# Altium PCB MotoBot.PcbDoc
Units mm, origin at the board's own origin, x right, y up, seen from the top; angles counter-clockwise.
Board outline 90.25 x 50.25 mm, 2 copper layers (Top Layer, Bottom Layer); 45 components, 34 nets, 155 pads, 10 vias.
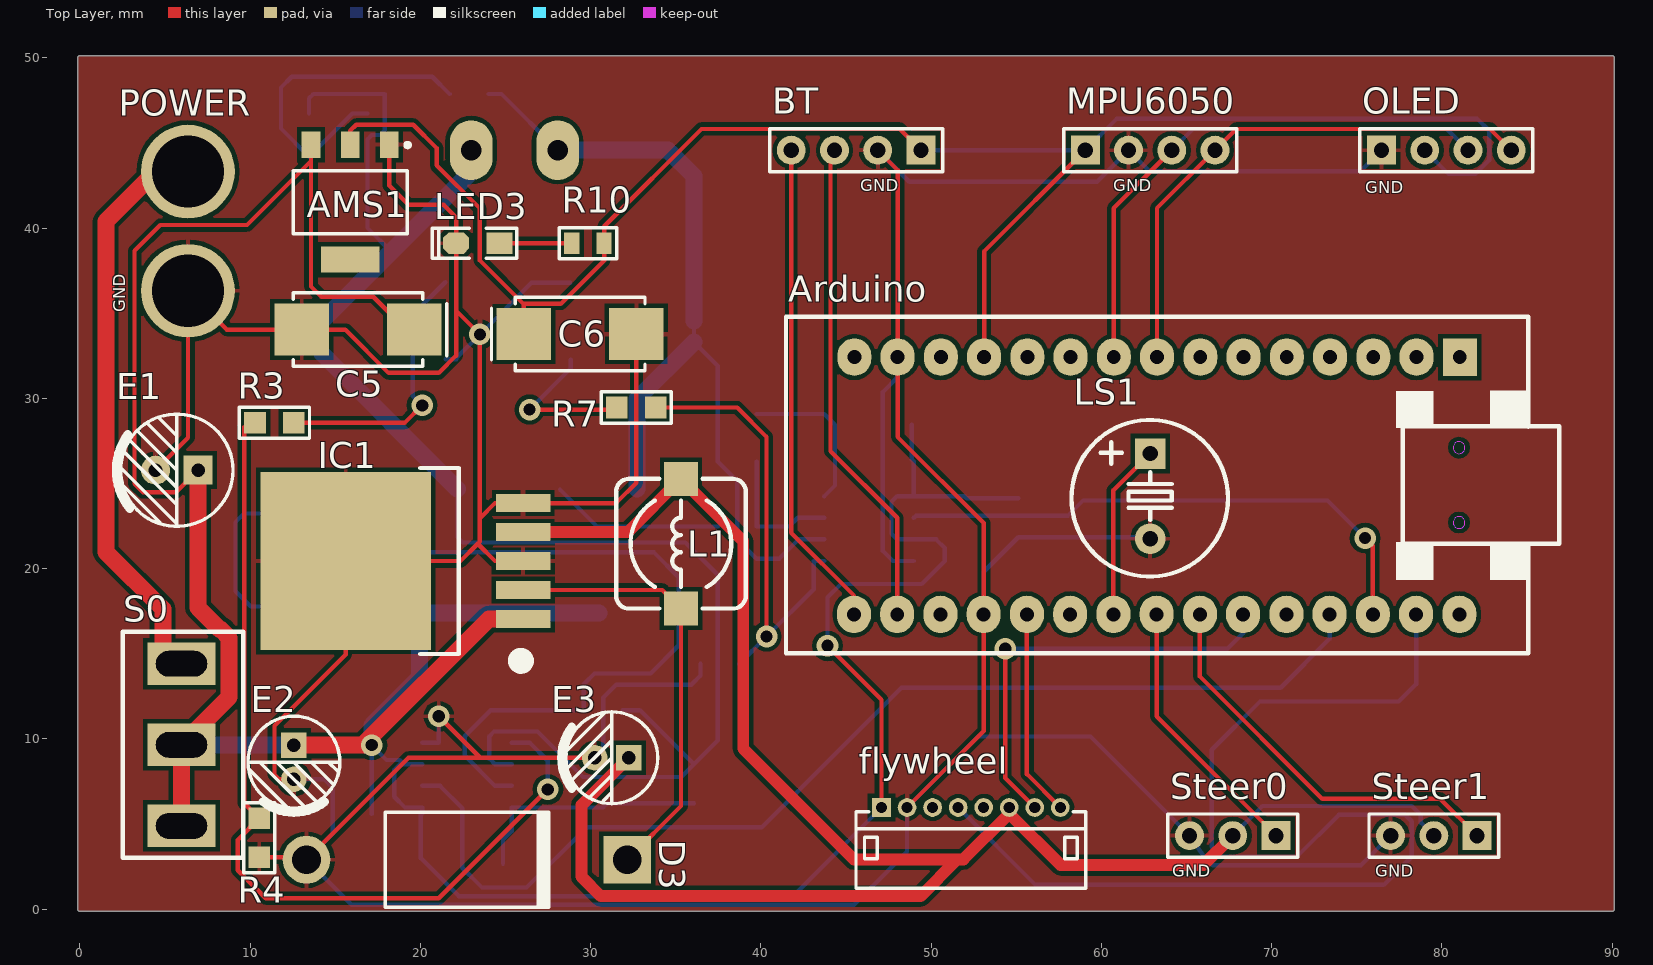
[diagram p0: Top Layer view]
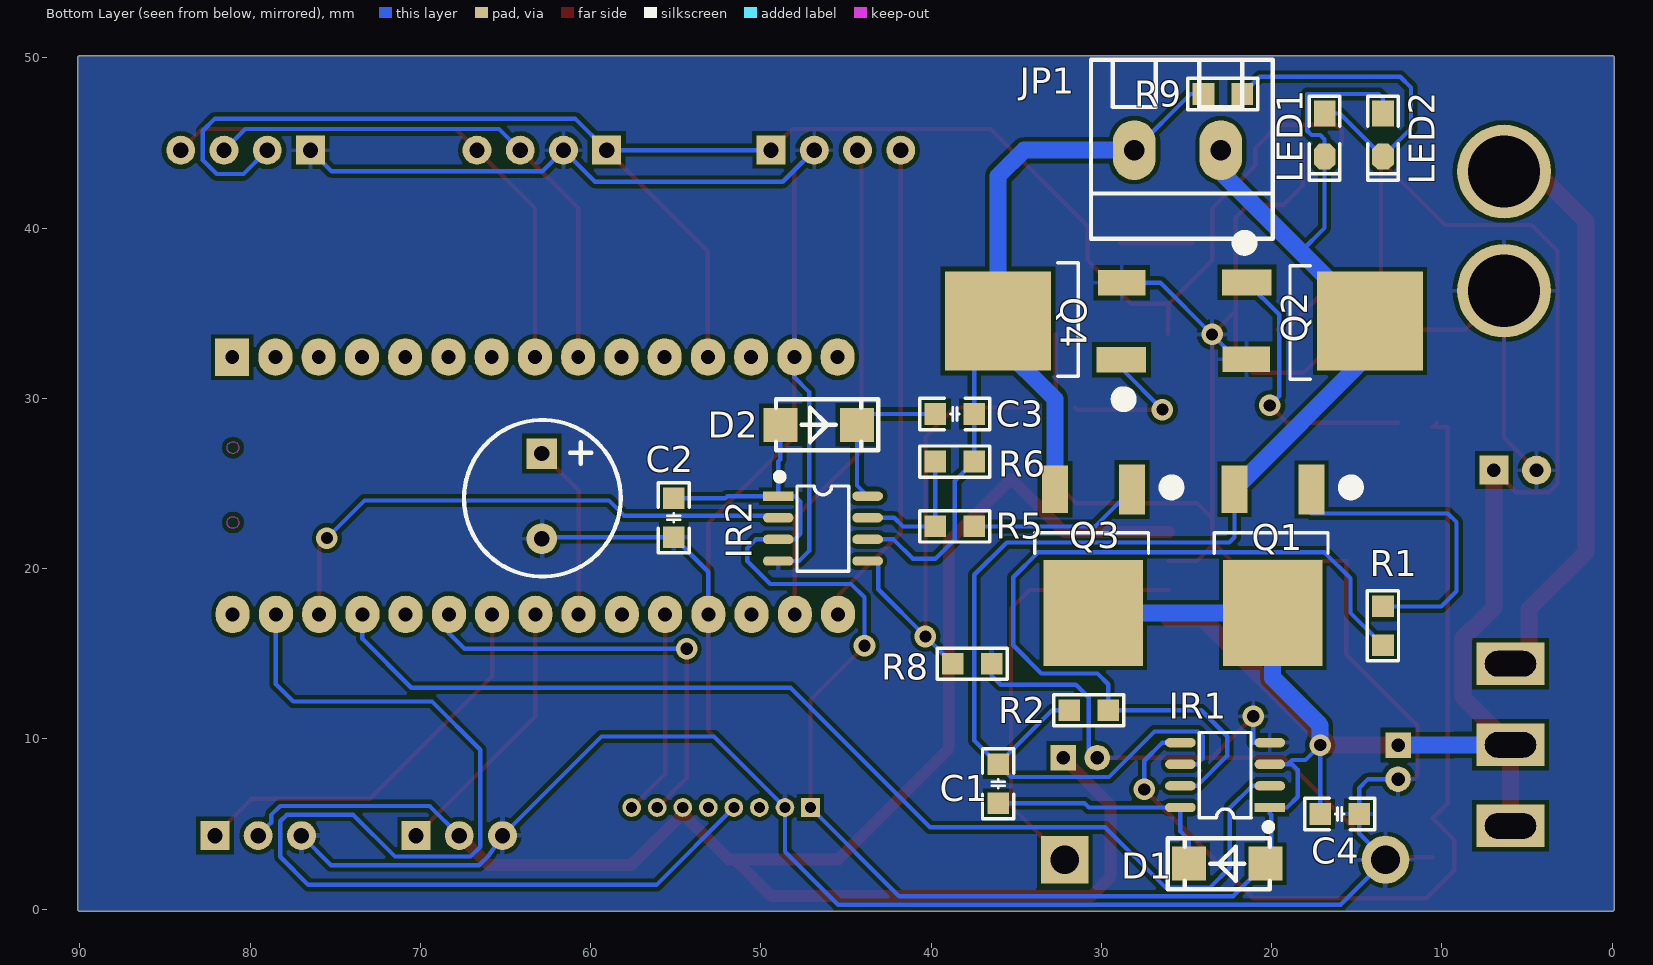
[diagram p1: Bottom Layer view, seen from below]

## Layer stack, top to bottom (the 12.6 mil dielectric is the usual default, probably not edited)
Top Solder: solder mask 0.0102, Solder Resist, Dk 3.5
Top Layer: signal copper 0.0356
Dielectric 1: dielectric 0.32, FR-4, Dk 4.8
Bottom Layer: signal copper 0.0356
Bottom Solder: solder mask 0.0102, Solder Resist, Dk 3.5

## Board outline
0,-0.127 cw(c0,0) -0.127,0 -0.127,50 cw(c0,50) 0,50.127 90,50.127 cw(c90,50) 90.127,50 90.127,0 cw(c90,0) 90,-0.127

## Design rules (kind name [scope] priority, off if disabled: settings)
Clearance [All] p1: gap=0.254 ignorepadtopadclearanceinfootprint=FALSE except(0: Arc-Hole Track-Hole SMDPad-Hole THPad-Hole Via-Hole Fill-Hole Poly-Hole Region-Hole Text-Hole)
PolygonConnect [All] p1: connectstyle=Relief reliefconductorwidth=0.254 reliefentries=4 polygonreliefangle="90 Angle" airgapwidth=0.254
RoutingVias [All] p1: holewidth=0.711 width=1.27 viastyle="Through Hole" minholewidth=0.711 minwidth=1.27 maxholewidth=0.711 maxwidth=1.27
SolderMaskExpansion [All] p1: expansion=0.102
Width [All] p1: maxlimit=2 minlimit=0.254 preferedwidth=0.254 minimp=50.000000 maximp=50.000000 favimp=50.000000
30 further rules are at their usual default settings.

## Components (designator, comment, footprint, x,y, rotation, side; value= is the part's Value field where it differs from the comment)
AMS1 "AMS1117-5V" SOT-223 15.875,41.529 r180 top
Arduino "NANO" NANO 81.051,32.426 r270 top
BT "HDR-1X4" HDR-1X4_M 49.403,44.577 r180 top
C1 "1u" "C 0805_M" 36.068,7.366 r270 bottom
C2 "0.1u" "C 0805_M" 55.118,22.987 r90 bottom
C3 "1u" "C 0805_M" 38.608,29.083 r0 bottom
C4 "0.1u" "C 0805_M" 16.002,5.588 r0 bottom
C5 "Cap Pol" CAP-7343 16.334,34.036 r180 top value=10uF
C6 "Cap Pol" CAP-7343 29.386,33.782 r0 top value=10uF
D1 "SS14" SMA 22.606,2.667 r0 bottom
D2 "SS14" SMA 46.609,28.448 r180 bottom
D3 "Diode 1N5825" DO-201AD 22.733,2.9 r0 top
E1 "220uF/16V" "CAP 2.5*6.3*7" 5.695,25.781 r180 top
E2 "680uF/25V" "CAP 2.0*5*11" 12.573,8.636 r270 top
E3 "220uF/25V" "CAP 2.0*5*11" 31.242,8.89 r180 top
flywheel "HDR-1X8" ZH1.5-WI-8P 52.337,5.969 r0 top
IC1 "LM2596-5.0V" TO263-5A 26.035,20.447 r90 top
IR1 "IR2104" SOP8_N 22.733,7.874 r0 bottom
IR2 "IR2104" SOP8_N 46.355,22.352 r180 bottom
JP1 "HDR-1X2" KF128-5.08-2P 22.987,44.577 r0 bottom
L1 "33uH" CDRH74 35.306,21.463 r90 top
LED1 "" "LED 0805R" 16.891,45.466 r270 bottom
LED2 "" "LED 0805R" 13.462,45.466 r270 bottom
LED3 "红色" "LED 0805W" 23.368,39.116 r180 top
LS1 "DC5V" "BEEP 5x9x5.5" 62.865,24.257 r180 top
MPU6050 "HDR-1X4" HDR-1X4_M 59.055,44.577 r0 top
OLED "HDR-1X4" HDR-1X4_M 76.454,44.577 r0 top
POWER "XT60" XT60 6.35,43.322 r0 top
Q1 "IRLR7843" TO252 19.939,21.599 r0 bottom
Q2 "IRLR7843" TO252 18.415,34.544 r270 bottom
Q3 "IRLR7843" TO252 30.48,21.599 r0 bottom
Q4 "IRLR7843" TO252 31.868,34.544 r90 bottom
R1 "30" "R 0805_M" 13.462,16.637 r90 bottom
R2 "10K" "R 0805_M" 30.734,11.684 r180 bottom
R3 "30" "R 0805_M" 11.43,28.575 r0 top
R4 "10K" "R 0805_M" 10.541,4.191 r90 top
R5 "30" "R 0805_M" 38.608,22.479 r180 bottom
R6 "10K" "R 0805_M" 38.608,26.289 r0 bottom
R7 "30" "R 0805_M" 32.688,29.464 r180 top
R8 "10K" "R 0805_M" 37.592,14.414 r0 bottom
R9 "2K" "R 0805_M" 22.86,47.879 r180 bottom
R10 "200R" "R 0805_L" 29.845,39.116 r0 top
S0 "Switcher" ThreeSwitcher 5.969,14.414 r90 top
Steer0 "HDR-1X3" HDR-1X3 70.256,4.318 r180 top
Steer1 "HDR-1X3" HDR-1X3 82.067,4.318 r180 top

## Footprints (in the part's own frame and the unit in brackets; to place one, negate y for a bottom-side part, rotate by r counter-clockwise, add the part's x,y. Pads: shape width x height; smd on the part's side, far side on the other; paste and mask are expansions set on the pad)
"BEEP 5x9x5.5" [mm] "5*9*5.5mm(脚距,直径,高度)"
  rect 1.8x1.8 hole 0.9: 1(0,-2.5)
  round 1.8 hole 0.9: 2(0,2.5)
  silkscreen extent -4.58,-4.47 4.62,4.72, body extent -4.5,-4.5 4.5,4.5, height 5.45
"C 0805_M" [mil] "无极性贴片电容"
  rect 50x50 smd: 1(-45,0) 2(45,0)
  silkscreen extent -81,-36 81,36, body extent -39,-24 39,24, height 20
"CAP 2.0*5*11" [mm] "脚距2mm直径5mm高度11mm"
  rect 1.5x1.5 hole 0.8: 1(-1,0)
  round 1.5 hole 0.8: 2(1,0)
  silkscreen extent -2.7,-2.7 2.96,2.7, body extent -2.5,-2.5 2.51,2.5, height 11.04
"CAP 2.5*6.3*7" [mm] "脚距2.5mm直径6.3mm高度7mm"
  rect 1.7x1.7 hole 0.8: 1(-1.25,0)
  round 1.7 hole 0.8: 2(1.25,0)
  silkscreen extent -3.3,-3.3 3.56,3.3, body extent -3.15,-3.15 3.16,3.15, height 7.03
CAP-7343 [mm] "钽电容"
  rect 3.2x3.05 smd: 1(-3.302,0) 2(3.302,0)
  silkscreen extent -5.21,-2.16 3.81,2.16, body extent -3.68,-1.91 3.68,1.91, height 2.95
CDRH74 [mm] "7.3*7.3*4.5mm（长宽高）"
  rect 2x2 smd: 1(-3.81,0) 2(3.81,0)
  silkscreen extent -3.81,-3.81 3.81,3.81, body extent -3.65,-3.65 3.65,3.65, height 4.5
DO-201AD [mm] "Diode, Axial; Body 9.5 x 5.6 mm (LxDia. max), Lead Dia. 1.32 mm (max)"
  round 2.8 hole 1.7: 1(-9.42,0)
  rect 2.8x2.8 hole 1.7: 2(9.42,0)
  silkscreen extent -4.8,-2.8 4.9,2.8
HDR-1X3 [mm] "排针，3脚"
  rect 1.7x1.7 hole 0.9: 1(0,0)
  round 1.7 hole 0.9: 2(2.54,0) 3(5.08,0)
  silkscreen extent -1.27,-1.27 6.35,1.27, body extent -1.27,-1.27 6.35,1.27, height 8.5
HDR-1X4_M [mm] "排母，4脚"
  rect 1.7x1.7 hole 0.9: 1(0,0)
  round 1.7 hole 0.9: 2(2.54,0) 3(5.08,0) 4(7.62,0)
  silkscreen extent -1.27,-1.27 8.89,1.27, body extent -1.27,-1.27 8.89,1.27, height 8.5
KF128-5.08-2P [mm] "螺钉式接线端子，脚距5.08mm"
  oval 2.5x3.5 hole 1.2: 1(0,0) 2(5.08,0)
  silkscreen extent -3.05,-5.31 7.62,5.21, body extent -3.04,-5.3 7.62,5.2, height 14.15
"LED 0805R" [mil] "红色0805LED"
  rect 60x50 smd: 1(-50,0)
  oct 60x50 smd: 2(50,0)
  silkscreen extent -90,-35 105,35, body extent -39,-25 39,25, height 32
"LED 0805W" [mil] "白色0805LED"
  rect 60x50 smd: 1(-50,0)
  oct 60x50 smd: 2(50,0)
  silkscreen extent -90,-35 105,35, body extent -39,-25 39,25, height 32
NANO [mm]
  oval 2.2x2 hole 0.813: 1(15.113,-35.585) 2(15.113,-33.045) 3(15.113,-30.505) 4(15.113,-27.965) 5(15.113,-25.425) 6(15.113,-22.885) 7(15.113,-20.345) 8(15.113,-17.805) 9(15.113,-15.265) 10(15.113,-12.725) 11(15.113,-10.185) 12(15.113,-7.645) 13(15.113,-5.105) 14(15.113,-2.565) 15(15.113,-0.025) 17(0,-2.54) 18(0,-5.08) 19(0,-7.62) 20(0,-10.16) 21(0,-12.7) 22(0,-15.24) 23(0,-17.78) 24(0,-20.32) 25(0,-22.86) 26(0,-25.4) 27(0,-27.94) 28(0,-30.48) 29(0,-33.02) 30(0,-35.56)
  rect 2.2x2 hole 0.813: 16(0,0)
  Keep-Out Layer circle w0.05: c5.319,-0.05 r0.35
  Keep-Out Layer circle w0.05: c9.719,-0.05 r0.35
  silkscreen extent -2.36,-39.57 17.4,5.85
"R 0805_L" [mil] "1/8W贴片电阻"
  rect 35x50 smd: 1(-37.4,0) 2(37.4,0)
  silkscreen extent -67,-36 67,36, body extent -39,-25 39,25, height 20
"R 0805_M" [mil] "1/8W贴片电阻"
  rect 50x50 smd: 1(-45,0) 2(45,0)
  silkscreen extent -81,-36 81,36, body extent -39,-25 39,25, height 20
SMA [mm]
  rect 2x2 smd: 1(-2.25,0) 2(2.25,0)
  silkscreen extent -2.5,-1.5 3.5,1.5, body extent -2.5,-1.35 2.5,1.35, height 2.15
SOP8_N [mm] "5*6*1.8mm（长宽高）"
  rect 1.8x0.55 smd: 1(-2.625,1.905)
  oval 1.8x0.55 smd: 2(-2.625,0.635) 3(-2.625,-0.635) 4(-2.625,-1.905) 5(2.625,-1.905) 6(2.625,-0.635) 7(2.625,0.635) 8(2.625,1.905)
  silkscreen extent -2.69,-2.5 1.52,3.2, body extent -3,-2.5 3,2.5, height 1.9
SOT-223 [mm]
  rect 1.1x1.55 smd: 1(-2.3,-3.375) 2(0,-3.375) 3(2.3,-3.375)
  rect 3.45x1.55 smd: 4(0,3.375)
  silkscreen extent -3.5,-3.48 3.35,1.85, body extent -3.3,-3.94 3.3,3.43, height 0.8
ThreeSwitcher [mm]
  rect 2.5x4 hole 1.5 slot 3 at 90 deg: 1(0,0) 2(-4.763,0) 3(-9.525,0)
  silkscreen extent -11.4,-3.62 1.87,3.45
TO252 [mil] "252晶体管"
  rect 60x115 smd: 1(-89.55,-119.77)
  rect 230x245 smd: 2(0,165.35)
  rect 60x110 smd: 3(88.45,-120.77)
  silkscreen extent -196,-140 135,28, body extent -127,-120 129,251, height 91
TO263-5A [mm] "263，5脚晶体管"
  rect 1.05x3.2 smd: 1(-3.4,0) 2(-1.7,0) 3(0,0) 4(1.7,0) 5(3.4,0)
  rect 10.45x10 smd: 3(0,10.414)
  silkscreen extent -6.24,-0.25 5.46,6.04, body extent -5,-0.01 5,13.32, height 4.5
XT60 [mm]
  round 5.5 hole 4.25: 0(0,0) 1(0,-7)
ZH1.5-WI-8P [mm] "长：13.5，宽：4.5，高：3.6"
  rect 1.1x1.1 hole 0.65: 1(-5.25,0)
  round 1.1 hole 0.65: 2(-3.75,0) 3(-2.25,0) 4(-0.75,0) 5(0.75,0) 6(2.25,0) 7(3.75,0) 8(5.25,0)
  silkscreen extent -6.75,-4.75 6.75,-0.25, body extent -6.75,-4.75 6.75,0.25, height 3.65

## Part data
AMS1: library part AMS1117, "三端稳压芯片"
BT MPU6050 OLED: library part "Header 4", "4P接插件"
C1 C2 C3 C4: library part C, "无极性贴片电容"
C5 C6: "极性电解电容"
D1 D2: "肖特基二极管"
D3: library part "Diode 1N5406", "是1N5825，不是1N5406"
E1 E2 E3: library part C-CAP, "直插电解电容"
flywheel: library part "Header 8", "8P接插件"
IC1: library part LM2596-5.0, "DC降压芯片"
IR1 IR2: "电机驱动芯片"
JP1: library part "Header 2", "2P接插件"
L1: library part Inductor
LED1 LED2 LED3: library part LED-SMD, "贴片LED"
LS1: library part BEEP, "蜂鸣器"
Q1 Q2 Q3 Q4: "N沟场效应管"
R1 R2 R3 R4 R5 R6 R7 R8 R9 R10: library part R, "贴片电阻"
S0: library part 3_Switcher
Steer0 Steer1: library part "Header 3", "3P接插件"

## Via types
v1: diameter 1.27, hole 0.711, Top Layer to Bottom Layer, 10 vias

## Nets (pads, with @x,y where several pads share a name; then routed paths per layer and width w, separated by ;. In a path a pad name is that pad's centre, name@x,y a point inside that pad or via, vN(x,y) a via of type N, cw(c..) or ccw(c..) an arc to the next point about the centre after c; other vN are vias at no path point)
3.3V: flywheel.3
+5: AMS1.2 Arduino.27 BT.1 C6.1 MPU6050.1 OLED.2 R10.2 | length 106.2
  Top Layer w0.254: AMS1.2 15.875,45.72 16.231,46.076 19.583,46.076 20.955,44.704 20.955,43.688 23.495,41.148 23.495,38.1 26.06,35.535 ; BT.1 48.158,45.822 36.51,45.822 30.795,40.107 R10.2 30.795,38.1 28.255,35.56 26.084,35.56 26.06,35.535 ; Arduino.27 53.111,38.633 MPU6050.1 ; 26.06,35.535 26.084,35.511 C6.1 26.06,35.535
  Bottom Layer w0.254: BT.1 MPU6050.1 60.909,46.431 82.067,46.431 82.779,45.72 82.779,43.993 81.966,43.18 80.391,43.18 OLED.2
"+5 POWER": E3.1 flywheel.6 IC1.4 L1.2 Steer0.2 Steer1.2 | length 107.9
  Top Layer w0.7: IC1.4 32.18,22.147 L1.2 38.964,21.615 38.964,9.423 45.466,2.921 51.539,2.921 ; E3.1 29.464,6.112 29.464,1.905 30.607,0.762 49.38,0.762 51.539,2.921 ; flywheel.6 flywheel.6@54.587,5.611 ; Steer0.2 65.989,2.591 57.607,2.591 flywheel.6@54.587,5.611 ; 51.539,2.921 51.898,2.921 flywheel.6@54.587,5.611
  Bottom Layer w0.254: Steer0.2 69.455,6.057 78.232,6.057 78.765,5.524 78.765,5.08 Steer1.2
+12: AMS1.3 C2.2 C4.2 C5.1 D1.1 D2.1 E1.1 E2.1 flywheel.1 IC1.1 IR1.1 IR1.3 IR2.1 IR2.3 Q1.2 Q3.2 S0.2 S0.3 | length 196.4
  Top Layer w0.254: AMS1.3 13.575,43.942 ; C5.1 19.165,34.036 17.235,35.966 14.185,35.966 13.575,36.576 13.575,43.942 ; v1(43.917,15.469) 47.087,12.298 flywheel.1 ; E1.1@6.934,25.77 6.934,25.781 E1.1 E1.1@6.934,25.77 ; E1.1@6.934,25.77 5.65,24.486 3.708,24.486 3.214,24.98 3.214,38.672 4.724,40.183 9.816,40.183 13.575,43.942
  Top Layer w1: S0.3 S0.2 8.771,12.454 8.771,15.929 8.281,16.419 8.219,16.419 6.934,17.704 E1.1@6.934,25.77 ; E2.1 v1@16.621,9.636 ; v1(17.145,9.636) v1@16.621,9.636 ; IC1.1 24.032,17.047 v1@16.621,9.636
  Bottom Layer w0.254: C4.2 v1(17.145,9.636) 18.018,8.763 18.796,8.763 19.05,8.509 ; IR1.3 19.05,8.509 ; v1(43.917,15.469) 43.917,18.313 44.704,19.101 49.454,19.101 50.8,20.447 50.8,21.209 50.292,21.717 IR2.3 48.006,21.717 47.676,22.047 47.676,23.927 48.006,24.257 IR2.1 ; flywheel.1 41.88,0.762 22.261,0.762 D1.1 20.025,2.998 20.025,5.535 20.108,5.618 IR1.1 19.101,5.969 18.466,6.604 18.466,8.179 18.796,8.509 19.05,8.509 ; D2.1 48.859,26.41 48.98,26.289 IR2.1 ; C2.2 52.095,24.13 51.968,24.257 IR2.1
  Bottom Layer w1: S0.2 9.271,9.652 9.287,9.636 E2.1 ; v1(17.145,9.636) 17.145,10.795 19.939,13.589 Q1.2 Q3.2
A_PHASE: Arduino.5 flywheel.8 | length 12.2
  Top Layer w0.254: Arduino.5 55.626,7.93 flywheel.8
B_PHASE: Arduino.10 flywheel.7 | length 25.5
  Top Layer w0.254: v1(54.356,15.291) 54.356,7.7 flywheel.7
  Bottom Layer w0.254: v1(54.356,15.291) 67.412,15.291 68.326,16.205 Arduino.10
BEEP: Arduino.7 LS1.1 | length 10.3
  Top Layer w0.254: Arduino.7 60.706,24.598 LS1.1
GND: AMS1.1 Arduino.4 Arduino.29 BT.2 C2.1 C4.1 C5.2 C6.2 D3.1 E1.2 E2.2 E3.2 flywheel.2 IC1.3 IC1.5 IR1.4 IR2.4 LED3.2 LS1.2 MPU6050.2 OLED.1 POWER.1 Q2.3 Q4.3 R4.1 R8.1 Steer0.3 Steer1.3 | length 336.7
  Top Layer w0.254: E1.2 6.35,27.686 POWER.1 8.636,34.036 C5.2 15.596,34.036 18.136,31.496 21.082,31.496 22.098,32.512 22.098,35.154 ; R4.1 13.165,3.048 D3.1 19.303,8.89 23.52,8.89 ; E2.2 11.684,7.636 11.43,7.89 11.43,10.77 15.621,14.961 15.621,20.447 22.352,20.447 23.368,21.463 ; AMS1.1 18.175,42.503 19.304,41.374 21.364,41.374 22.098,40.64 LED3.2 22.098,35.154 ; v1(21.082,11.328) 23.52,8.89 ; IC1.3@26.035,20.447 24.384,20.447 23.368,21.463 ; E3.2 23.52,8.89 ; C6.2 32.688,25.039 31.496,23.847 IC1.5 24.38,23.847 23.495,22.962 ; BT.2 48.031,43.409 Arduino.29 48.031,27.737 53.086,22.682 Arduino.4 53.086,10.468 flywheel.2 ; 22.098,35.154 v1(23.495,33.757) 23.495,22.962 ; 23.368,21.463 23.495,21.59 23.495,22.962
  Bottom Layer w0.254: E2.2 14.335,7.636 14.859,7.112 C4.1 14.859,4.446 D3.1 15.959,0.254 45.466,0.254 48.587,3.375 flywheel.2 52.753,10.135 59.36,10.135 Steer0.3 65.977,3.15 66.548,2.579 75.248,2.579 Steer1.3 ; IR1.4 21.082,9.779 v1(21.082,11.328) ; Q2.3 22.123,32.297 22.123,32.385 v1(23.495,33.757) 26.529,36.791 Q4.3 ; E3.2 30.734,9.382 30.734,12.421 31.496,13.183 35.916,13.183 36.449,13.716 R8.1 ; BT.2 48.717,42.723 59.741,42.723 MPU6050.2 62.84,43.332 75.209,43.332 OLED.1 ; Arduino.29 48.031,31.242 47.168,30.378 47.168,21.031 47.752,20.447 IR2.4 ; Arduino.4 53.086,19.812 C2.1 62.778,21.844 LS1.2
MOTOR1: C1.1 IR1.6 JP1.1 LED1.2 LED2.1 Q1.3 Q2.2 R2.1 | length 95.4
  Bottom Layer w0.254: LED2.1 13.462,47.625 13.716,47.879 17.907,47.879 17.907,45.72 17.653,45.466 17.145,45.466 16.891,45.212 LED1.2 16.891,40.014 18.288,38.617 ; Q2.2@14.215,32.637 Q2.2 ; Q1.3 22.186,21.844 22.49,21.539 35.56,21.539 37.465,19.634 37.465,9.906 C1.1 ; JP1.1@22.987,43.316 JP1.1 ; IR1.6 24.384,8.509 24.054,8.839 24.054,10.16 24.329,10.435 26.878,10.435 29.554,7.759 35.318,7.759 C1.1 ; R2.1 32.893,11.684 C1.1
  Bottom Layer w1: Q2.2@14.215,32.637 Q1.3 ; Q2.2 18.288,38.617 JP1.1@22.987,43.316
MOTOR2: C3.1 IR2.6 JP1.2 Q3.3 Q4.2 R6.1 R9.1 | length 52.5
  Bottom Layer w0.254: R9.1 24.765,47.879 JP1.2 ; Q4.2 36.068,33.299 37.465,31.902 C3.1 R6.1 38.608,25.146 38.608,21.717 39.751,20.574 41.072,20.574 42.215,21.717 IR2.6
  Bottom Layer w1: JP1.2 34.544,44.577 36.068,43.053 Q4.2 ; Q3.3 32.727,29.958 Q4.2@36.068,33.299
Motor_DIR: flywheel.5
NetC1_2: C1.2 D1.2 IR1.8 | length 14.3
  Bottom Layer w0.254: D1.2 24.856,4.064 25.358,4.566 IR1.8 30.734,5.969 30.988,6.223 C1.2
NetC3_2: C3.2 D2.2 IR2.8 | length 9.3
  Bottom Layer w0.254: C3.2 43.724,29.083 D2.2 44.359,24.886 IR2.8
NetD3_2: D3.2 IC1.2 L1.1 | length 25.8
  Top Layer w0.254: IC1.2 34.212,18.747 L1.1 35.306,6.053 D3.2
NetIR1_5: IR1.5 R3.1 R4.2 | length 54
  Top Layer w0.254: R3.1 10.541,28.321 9.652,28.321 9.652,6.223 R4.2 9.271,4.064 9.271,2.286 10.922,0.635 21.082,0.635 v1(27.483,7.036)
  Bottom Layer w0.254: IR1.5 26.416,9.779 27.483,8.712 v1(27.483,7.036)
NetIR1_7: IR1.7 R1.1 R2.2 | length 50.1
  Bottom Layer w0.254: R1.1 15.367,17.399 15.367,19.431 16.891,20.955 33.718,20.955 35.179,19.494 35.179,15.494 33.528,13.843 30.226,13.843 29.591,13.208 R2.2 24.13,11.684 22.606,10.16 22.606,9.017 24.384,7.239 IR1.7
NetIR2_5: IR2.5 R7.1 R8.2 | length 27.4
  Top Layer w0.254: R7.1 38.608,29.464 40.335,27.737 v1(40.335,16.015)
  Bottom Layer w0.254: R8.2 v1(40.335,16.015) 43.104,18.783 43.104,20.447 IR2.5
NetIR2_7: IR2.7 R5.1 R6.2 | length 8
  Bottom Layer w0.254: R6.2 R5.1 41.656,22.479 42.164,22.987 IR2.7
NetLED1_1: LED1.1 LED2.2 R9.2 | length 19.8
  Bottom Layer w0.254: LED1.1 16.002,46.736 LED2.2 11.811,45.847 11.811,48.26 12.446,48.895 20.701,48.895 R9.2
NetLED3_1: LED3.1 R10.1 | length 4.3
  Top Layer w0.254: LED3.1 26.746,39.116 R10.1
NetPOWER_0: POWER.0 S0.1 | length 34.5
  Top Layer w1: S0.1 4.877,14.414 4.877,17.628 1.524,20.98 1.524,40.386 4.46,43.322 POWER.0
NetQ1_1: Q1.1 R1.2 | length 18.9
  Bottom Layer w0.254: R1.2 10.033,17.78 9.144,18.669 9.144,22.733 9.652,23.241 17.664,23.241 Q1.1
NetQ2_1: Q2.1 R3.2 | length 16.2
  Top Layer w0.254: R3.2 19.092,28.575 v1(20.108,29.591)
  Bottom Layer w0.254: v1(20.108,29.591) 19.558,30.141 19.558,34.919 Q2.1
NetQ3_1: Q3.1 R5.2 | length 10.2
  Bottom Layer w0.254: Q3.1 30.368,22.479 R5.2
NetQ4_1: Q4.1 R7.2 | length 9.1
  Top Layer w0.254: v1(26.416,29.337) 31.418,29.337 R7.2
  Bottom Layer w0.254: v1(26.416,29.337) 28.826,31.747 Q4.1
PWM0: Arduino.8 Steer0.1 | length 15.9
  Top Layer w0.254: Arduino.8 63.246,11.328 Steer0.1
PWM1: Arduino.9 Steer1.1 | length 23.8
  Top Layer w0.254: Arduino.9 65.786,13.665 72.974,6.477 79.908,6.477 Steer1.1
PWM2: Arduino.12 IR1.2 | length 65.3
  Bottom Layer w0.254: IR1.2 21.158,7.239 22.464,5.933 22.464,2.428 23.622,1.27 26.238,1.27 29.769,4.801 40.056,4.801 48.26,13.005 70.536,13.005 73.406,15.875 Arduino.12
PWM3: Arduino.13 IR2.2 | length 32.5
  Top Layer w0.254: v1(75.489,21.793) 75.946,21.336 Arduino.13
  Bottom Layer w0.254: IR2.2 49.107,23.114 58.039,23.114 58.928,24.003 73.279,24.003 v1(75.489,21.793)
PWM4: Arduino.14 flywheel.4 | length 67.9
  Bottom Layer w0.254: flywheel.4 56.134,1.422 76.581,1.422 78.232,3.073 78.232,5.156 77.839,5.549 73.95,5.549 71.487,3.087 67.056,3.087 66.485,3.658 66.485,9.361 69.317,12.192 77.47,12.192 78.486,13.208 Arduino.14
SCL: Arduino.24 MPU6050.3 OLED.3 | length 32
  Top Layer w0.254: Arduino.24 60.731,41.173 MPU6050.3
  Bottom Layer w0.254: MPU6050.3 65.38,45.822 80.289,45.822 OLED.3
SDA: Arduino.23 MPU6050.4 OLED.4 | length 32
  Top Layer w0.254: Arduino.23 63.271,41.173 MPU6050.4 67.92,45.822 82.829,45.822 OLED.4
UART0_RX: Arduino.2 BT.3 | length 29.1
  Top Layer w0.254: BT.3 44.094,44.577 44.094,26.899 48.006,22.987 Arduino.2
UART0_TX: Arduino.1 BT.4 | length 28.8
  Top Layer w0.254: BT.4 41.783,22.098 45.466,18.415 Arduino.1
pads on no net: AMS1.4 Arduino.3 Arduino.6 Arduino.11 Arduino.15 Arduino.16 Arduino.17 Arduino.18 Arduino.19 Arduino.20 Arduino.21 Arduino.22 Arduino.25 Arduino.26 Arduino.28 Arduino.30

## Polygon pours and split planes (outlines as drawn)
GND on Top Layer "Top Layer-No Net" (solid, pour order 0): 0,-0.127 cw(c0,0) -0.127,0 -0.127,50 cw(c0,50) 0,50.127 90,50.127 cw(c90,50) 90.127,50 90.127,0 cw(c90,0) 90,-0.127
GND on Bottom Layer "Top Layer-No Net1" (solid, pour order 1): 0,-0.127 cw(c0,0) -0.127,0 -0.127,50 cw(c0,50) 0,50.127 90,50.127 cw(c90,50) 90.127,50 90.127,0 cw(c90,0) 90,-0.127

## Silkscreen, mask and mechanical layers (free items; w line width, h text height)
Top Overlay:
  text "GND" at 45.847,42.164 h0.7
  text "GND" at 60.706,42.164 h0.7
  text "GND" at 75.489,42.037 h0.7
  text "GND" at 2.667,35.052 h0.7 r90
  text "GND" at 64.16,1.905 h0.7
  text "GND" at 76.098,1.905 h0.7
Mechanical 1:
  lines w0.254: 0,50 90,50 ; 0,50 90,50 ; 0,50 0,0 90,0 90,50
